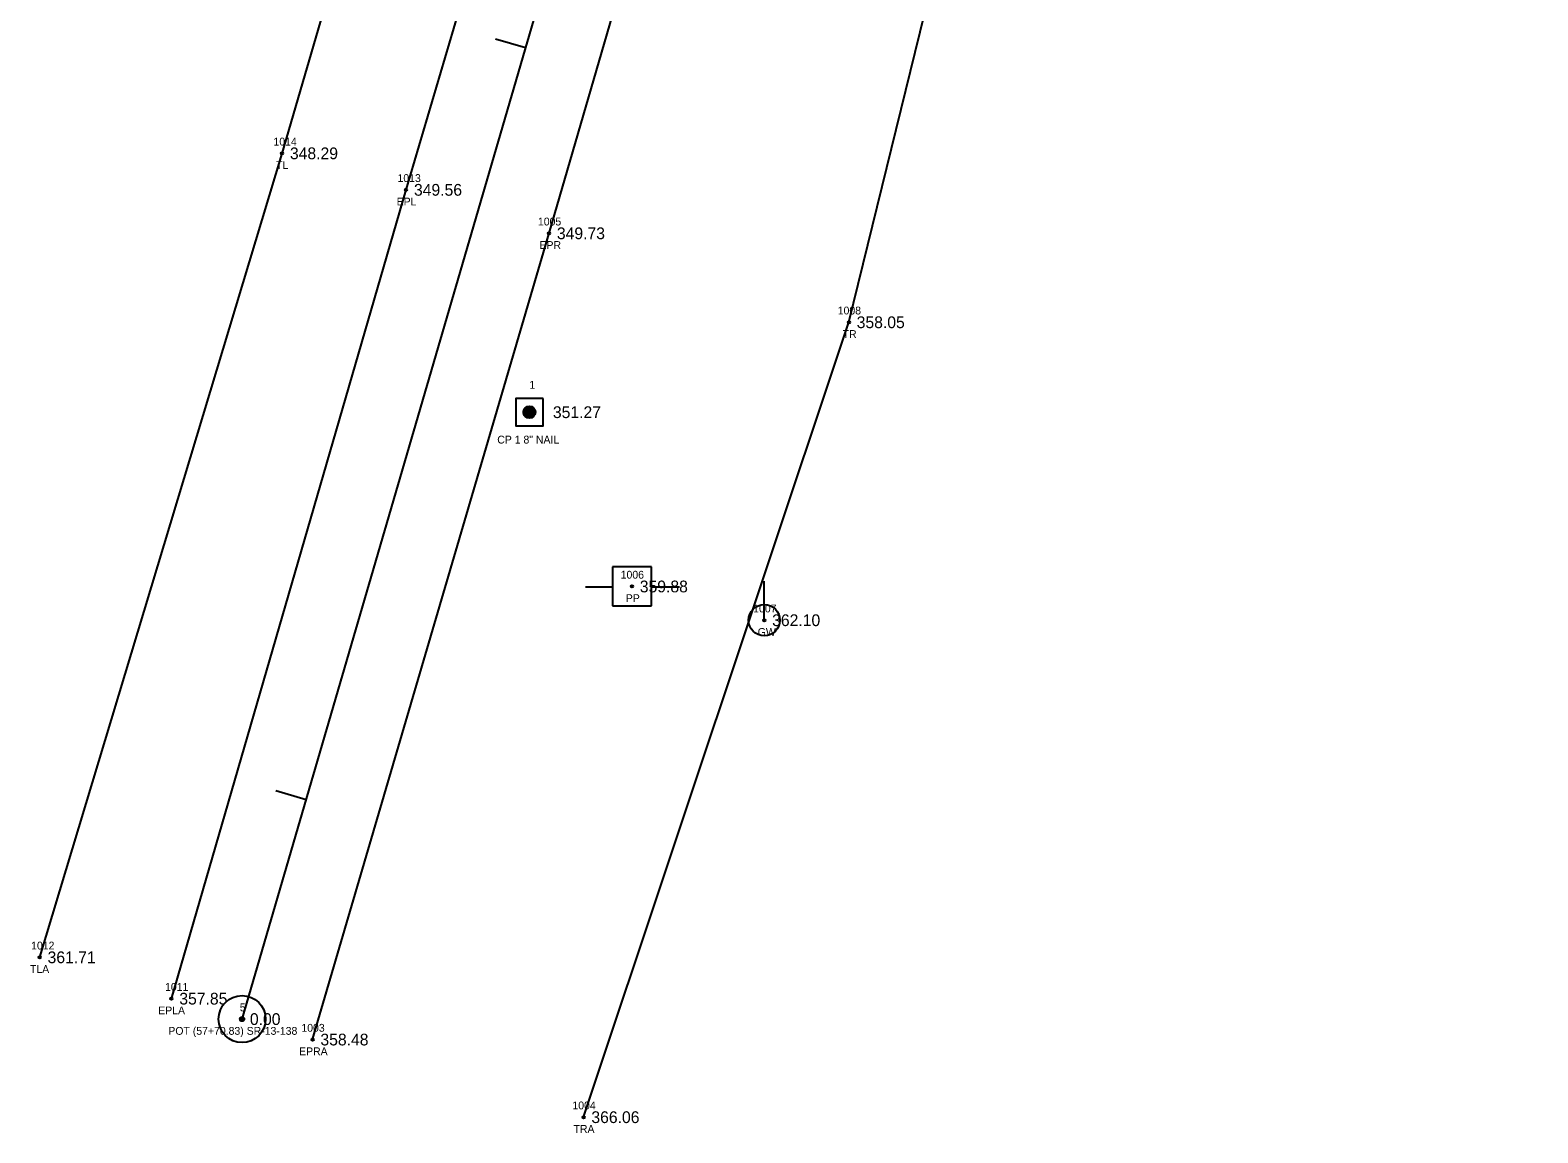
# Model space of a CAD drawing. Extents: x 2231119 to 2232595, y 1035731 to 1037094.
# Drawn here: x 2231140.4 to 2231332.8, y 1035731 to 1035871.8 of the extents above; entities that cross this region are included whole.
import ezdxf

# ---------------------------------------------------------------- set-up
doc = ezdxf.new("R2010")
doc.units = 0
for name, color, linetype in [('RD_EX_Road', 7, 'Continuous'), ('RD_EX_Road_txCode', 7, 'Continuous'), ('RD_EX_TX_Road_ELEV', 7, 'Continuous'), ('RD_EX_TX_UT_ELEV', 7, 'Continuous'), ('RD_EX_TX_VEG_ELEV', 7, 'Continuous'), ('RD_EX_UT', 7, 'Continuous'), ('RD_EX_UT_txCode', 7, 'Continuous'), ('RD_EX_VEG', 7, 'Continuous'), ('RD_EX_VEG_txCode', 7, 'Continuous'), ('RD_HC_Cl', 7, 'Continuous'), ('RD_HC_Data', 7, 'Continuous'), ('RD_HC_Data_Tic', 7, 'Continuous'), ('RD_HC_Survey', 7, 'Continuous'), ('RD_HC_Survey_ELEV', 7, 'Continuous'), ('RD_HC_Survey_txCode', 7, 'Continuous'), ('RD_HC_txCode', 7, 'Continuous'), ('RD_SMD_Locator', 7, 'Continuous')]:
    doc.layers.add(name, color=color, linetype=linetype)

msp = doc.modelspace()

# ---------------------------------------------------------------- linework, layer by layer
at = {"layer": 'RD_EX_Road'}
for points in [[(2231158.42, 1035748.11), (2231188.37, 1035851.38), (2231216.59, 1035946.92), (2231244.77, 1036040.72), (2231278.59, 1036133.31), (2231299.55, 1036179.73), (2231323.11, 1036221.2), (2231350.7, 1036262.3), (2231381.59, 1036299.29), (2231415.97, 1036336.9), (2231452.94, 1036369.74), (2231498.19, 1036405.3), (2231537.2, 1036432.57), (2231541.46, 1036424.96)], [(2231176.43, 1035742.89), (2231206.61, 1035845.83), (2231234.19, 1035940.65), (2231261.92, 1036033.75), (2231294.68, 1036125.28), (2231316.11, 1036171.75), (2231338.19, 1036211.09), (2231363.83, 1036252.38), (2231394.08, 1036289.28), (2231427.67, 1036324.2), (2231464.37, 1036355.5), (2231508.96, 1036392.41), (2231546.55, 1036416.22), (2231541.46, 1036424.96)]]:
    msp.add_lwpolyline(points, dxfattribs=at)
at = {"layer": 'RD_EX_UT'}
for p, q in [((2231219.69, 1035803.25), (2231214.69, 1035803.25)), ((2231214.69, 1035803.25), (2231214.69, 1035798.25)), ((2231219.69, 1035798.25), (2231219.69, 1035803.25)), ((2231234.08, 1035796.43), (2231234.08, 1035801.43)), ((2231211.25, 1035800.68), (2231214.72, 1035800.68)), ((2231219.61, 1035800.68), (2231223.25, 1035800.68)), ((2231214.69, 1035798.25), (2231219.69, 1035798.25))]:
    msp.add_line(p, q, dxfattribs=at)
msp.add_circle((2231234.08, 1035796.43), 2, dxfattribs=at)
at = {"layer": 'RD_EX_VEG'}
for points in [[(2231141.61, 1035753.39), (2231172.54, 1035856.04), (2231200.09, 1035950.41), (2231226.19, 1036046.04), (2231262.9, 1036139.62), (2231281.03, 1036187.82), (2231303.66, 1036232.51), (2231318.61, 1036284.65), (2231353.84, 1036322.59), (2231394.02, 1036358.2), (2231443.85, 1036383.78)], [(2231211.01, 1035732.98), (2231244.87, 1035834.47), (2231267.87, 1035928.24), (2231283.13, 1036029.08), (2231316.25, 1036116.26), (2231338.15, 1036162.94), (2231357.98, 1036198.54), (2231413.07, 1036272.2), (2231445.22, 1036302.16), (2231483.09, 1036338.47), (2231530.02, 1036372.29)]]:
    msp.add_lwpolyline(points, dxfattribs=at)
at = {"layer": 'RD_HC_Cl'}
msp.add_line((2231167.43, 1035745.5), (2231256.91, 1036052.22), dxfattribs=at)
at = {"layer": 'RD_HC_Data'}
for radius in [3, 0.282]:
    msp.add_circle((2231167.43, 1035745.5), radius, dxfattribs=at)
at = {"layer": 'RD_HC_Data_Tic'}
for p, q in [((2231203.61, 1035869.5), (2231199.77, 1035870.62)), ((2231175.6, 1035773.5), (2231171.76, 1035774.63))]:
    msp.add_line(p, q, dxfattribs=at)
at = {"layer": 'RD_HC_Survey'}
for p, q in [((2231203.35, 1035822.81), (2231203.35, 1035823.17)), ((2231203.37, 1035822.73), (2231203.37, 1035823.25)), ((2231203.4, 1035822.67), (2231203.4, 1035823.31)), ((2231203.42, 1035822.62), (2231203.42, 1035823.36)), ((2231203.45, 1035822.58), (2231203.45, 1035823.4)), ((2231203.47, 1035822.54), (2231203.47, 1035823.44)), ((2231203.5, 1035822.51), (2231203.5, 1035823.47)), ((2231203.52, 1035822.48), (2231203.52, 1035823.5)), ((2231203.55, 1035822.45), (2231203.55, 1035823.53)), ((2231203.57, 1035822.43), (2231203.57, 1035823.55)), ((2231203.6, 1035822.41), (2231203.6, 1035823.58)), ((2231203.62, 1035822.39), (2231203.62, 1035823.6)), ((2231203.65, 1035822.37), (2231203.65, 1035823.61)), ((2231203.67, 1035822.35), (2231203.67, 1035823.63)), ((2231203.7, 1035822.33), (2231203.7, 1035823.65)), ((2231203.72, 1035822.32), (2231203.72, 1035823.66)), ((2231203.75, 1035822.31), (2231203.75, 1035823.68)), ((2231203.77, 1035822.29), (2231203.77, 1035823.69)), ((2231203.79, 1035822.28), (2231203.79, 1035823.7)), ((2231203.82, 1035822.27), (2231203.82, 1035823.71)), ((2231203.84, 1035822.26), (2231203.84, 1035823.72)), ((2231203.87, 1035822.26), (2231203.87, 1035823.73)), ((2231203.89, 1035822.25), (2231203.89, 1035823.73)), ((2231203.92, 1035822.24), (2231203.92, 1035823.74)), ((2231203.94, 1035822.24), (2231203.94, 1035823.74)), ((2231203.97, 1035822.23), (2231203.97, 1035823.75)), ((2231203.99, 1035822.23), (2231203.99, 1035823.75)), ((2231204.02, 1035822.23), (2231204.02, 1035823.76)), ((2231204.04, 1035822.22), (2231204.04, 1035823.76)), ((2231204.07, 1035822.22), (2231204.07, 1035823.76)), ((2231204.09, 1035822.22), (2231204.09, 1035823.76)), ((2231204.12, 1035822.22), (2231204.12, 1035823.76)), ((2231204.14, 1035822.22), (2231204.14, 1035823.76)), ((2231204.17, 1035822.22), (2231204.17, 1035823.76)), ((2231204.19, 1035822.23), (2231204.19, 1035823.75)), ((2231204.22, 1035822.23), (2231204.22, 1035823.75)), ((2231204.24, 1035822.23), (2231204.24, 1035823.75)), ((2231204.26, 1035822.24), (2231204.26, 1035823.74)), ((2231204.29, 1035822.25), (2231204.29, 1035823.74)), ((2231204.31, 1035822.25), (2231204.31, 1035823.73)), ((2231204.34, 1035822.26), (2231204.34, 1035823.72)), ((2231204.36, 1035822.27), (2231204.36, 1035823.71)), ((2231204.39, 1035822.28), (2231204.39, 1035823.7)), ((2231204.41, 1035822.29), (2231204.41, 1035823.69)), ((2231204.44, 1035822.3), (2231204.44, 1035823.68)), ((2231204.46, 1035822.31), (2231204.46, 1035823.67)), ((2231204.49, 1035822.33), (2231204.49, 1035823.65)), ((2231204.51, 1035822.34), (2231204.51, 1035823.64)), ((2231204.54, 1035822.36), (2231204.54, 1035823.62)), ((2231204.56, 1035822.38), (2231204.56, 1035823.6)), ((2231204.59, 1035822.4), (2231204.59, 1035823.59)), ((2231204.61, 1035822.42), (2231204.61, 1035823.56)), ((2231204.64, 1035822.44), (2231204.64, 1035823.54)), ((2231204.66, 1035822.47), (2231204.66, 1035823.52)), ((2231204.69, 1035822.49), (2231204.69, 1035823.49)), ((2231204.71, 1035822.53), (2231204.71, 1035823.46)), ((2231204.73, 1035822.56), (2231204.73, 1035823.42)), ((2231204.76, 1035822.6), (2231204.76, 1035823.38)), ((2231204.78, 1035822.64), (2231204.78, 1035823.34)), ((2231204.81, 1035822.7), (2231204.81, 1035823.28)), ((2231204.83, 1035822.77), (2231204.83, 1035823.21)), ((2231204.86, 1035822.88), (2231204.86, 1035823.1))]:
    msp.add_line(p, q, dxfattribs=at)
msp.add_lwpolyline([(2231205.85, 1035824.74), (2231202.35, 1035824.74), (2231202.35, 1035821.24), (2231205.85, 1035821.24)], close=True, dxfattribs=at)
msp.add_circle((2231204.1, 1035822.99), 0.769, dxfattribs=at)
at = {"layer": 'RD_SMD_Locator'}
for centre in [(2231172.54, 1035856.04), (2231188.37, 1035851.38), (2231206.61, 1035845.83), (2231244.87, 1035834.47), (2231204.1, 1035822.99), (2231217.19, 1035800.74), (2231234.08, 1035796.43), (2231141.61, 1035753.39), (2231158.42, 1035748.11), (2231167.43, 1035745.5), (2231176.43, 1035742.89), (2231211.01, 1035732.98)]:
    msp.add_circle(centre, 0.15, dxfattribs=at)

# ---------------------------------------------------------------- texts
at = {"layer": 'RD_EX_Road_txCode'}
for s, p in [('1013', (2231187.27, 1035852.38)), ('EPL', (2231187.16, 1035849.38)), ('1005', (2231205.19, 1035846.83)), ('EPR', (2231205.39, 1035843.83)), ('1011', (2231157.6, 1035749.11)), ('EPLA', (2231156.73, 1035746.11)), ('1003', (2231175, 1035743.89)), ('EPRA', (2231174.71, 1035740.89))]:
    msp.add_text(s, height=1, dxfattribs=at).set_placement(p)
at = {"layer": 'RD_EX_TX_Road_ELEV'}
for s, p in [('349.56', (2231189.37, 1035850.63)), ('349.73', (2231207.61, 1035845.08)), ('357.85', (2231159.42, 1035747.36)), ('358.48', (2231177.43, 1035742.14))]:
    msp.add_text(s, height=1.5, dxfattribs=at).set_placement(p)
at = {"layer": 'RD_EX_TX_UT_ELEV'}
msp.add_text('362.10', height=1.5, dxfattribs=at).set_placement((2231235.08, 1035795.68))
at = {"layer": 'RD_EX_TX_VEG_ELEV'}
for s, p in [('348.29', (2231173.54, 1035855.29)), ('358.05', (2231245.87, 1035833.72)), ('361.71', (2231142.61, 1035752.64)), ('366.06', (2231212.01, 1035732.23))]:
    msp.add_text(s, height=1.5, dxfattribs=at).set_placement(p)
at = {"layer": 'RD_EX_UT_txCode'}
for s, p in [('1006', (2231215.75, 1035801.74)), ('PP', (2231216.41, 1035798.74)), ('1007', (2231232.66, 1035797.43)), ('GW', (2231233.24, 1035794.43))]:
    msp.add_text(s, height=1, dxfattribs=at).set_placement(p)
at = {"layer": 'RD_EX_VEG_txCode'}
for s, p in [('1014', (2231171.44, 1035857.04)), ('TL', (2231171.77, 1035854.04)), ('1008', (2231243.45, 1035835.47)), ('TR', (2231244.08, 1035832.47)), ('1012', (2231140.51, 1035754.39)), ('TLA', (2231140.36, 1035751.39)), ('1004', (2231209.59, 1035733.98)), ('TRA', (2231209.73, 1035730.98))]:
    msp.add_text(s, height=1, dxfattribs=at).set_placement(p)
at = {"layer": 'RD_HC_Survey_ELEV'}
for s, p in [('351.27', (2231207.1, 1035822.24)), ('359.88', (2231218.19, 1035799.99)), ('0.00', (2231168.43, 1035744.75))]:
    msp.add_text(s, height=1.5, dxfattribs=at).set_placement(p)
at = {"layer": 'RD_HC_Survey_txCode'}
for s, p in [('1', (2231204.1, 1035825.99)), ('CP 1 8" NAIL', (2231200, 1035818.99))]:
    msp.add_text(s, height=1, dxfattribs=at).set_placement(p)
at = {"layer": 'RD_HC_txCode'}
for s, p in [('5', (2231167.14, 1035746.5)), ('POT (57+70.83) SR-13-138', (2231158.02, 1035743.5))]:
    msp.add_text(s, height=1, dxfattribs=at).set_placement(p)

doc.saveas('drawing.dxf')
